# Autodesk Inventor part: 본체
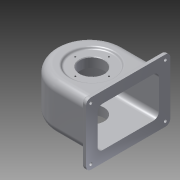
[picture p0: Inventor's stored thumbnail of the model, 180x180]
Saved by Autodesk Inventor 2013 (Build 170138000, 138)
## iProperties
Created: 2016-01
Part Number: 본체
Material: 알루미늄 6061
Document SubType Name: Modeling
Designer: dgall
Density: 2.71 g/cm^3
Mass: 812.893 g
Surface Area: 998.202 cm^2
Volume: 299.96 cm^3
Author: dgall
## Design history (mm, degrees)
sketch "스케치1"
  geometry: L1 (0, -57)-(64, -57); L2 (0, 57)-(64, 57); L3 (64, -57)-(64, 57); A1 r 57 centre (0, 0) between (0, 57) and (0, -57); 1 further point
  constraints: 6 end point, 2 point on circle, 2 tangent, 1 centre point, 1 coincident, 1 horizontal, 1 parallel, 1 perpendicular
  dimensions: "d4" = 114 diameter of A1; "d6" = 121 dimension on A1 L3
extrude "돌출1" new body sketch "스케치1" distance "d7" = 77; taper "d8" = 0 deg
feature "쉘1" dims "d9" = 6
sketch "스케치2"
  geometry: L1 (0, 0)-(64, 0) reference; L2 (0, -102)-(0, 0) reference; L3 (64, -102)-(0, -102) reference; A1 r 51 centre (64, -51) between (64, -102) and (64, 0) reference
extrude "돌출2" cut sketch "스케치2" distance "d10" = 1; taper "d11" = 0 deg
sketch "스케치3"
  geometry: L1 (64, 0)-(0, 0) reference; L2 (64, 102)-(64, 0) reference; L3 (0, 102)-(64, 102) reference; A1 r 51 centre (0, 51) between (0, 102) and (0, 0) reference
extrude "돌출3" cut sketch "스케치3" distance "d12" = 1; taper "d13" = 0 deg
sketch "스케치4"
  geometry: L1 (-64, 57)-(-64, -57) reference; L2 (-64, -57)-(0, -57) reference; L3 (-4, 24.205)-(-4, -25.457); L4 (0, 0)-(-23.424, 0); C1 r 31 at (-4, 0); A1 r 57 centre (0, 0) between (0, -57) and (0, 57) reference
  constraints: 4 end point, 2 perpendicular, 2 point on line, 1 centre point
  dimensions: "d131" = 60 distance between parallel lines of L1 L3; "d132" = 62 diameter of C1
extrude "돌출4" join sketch "스케치4" distance "d16" = 10; taper "d17" = 0 deg
sketch "스케치5"
  geometry: L1 (-4, 78.827)-(-4, -8.173); L2 (-64, 5)-(-64, 72) reference; L3 (-4, 58)-(16, 58); L4 (16, 58)-(16, 74); L5 (16, 58)-(24, 58); L6 (24, 58)-(35.747, 72); L7 (57, 77)-(0, 77) reference; L8 (-4, 74)-(30.899, 74); L9 (30.899, 74)-(33.416, 77); L10 (51, 72)-(0, 72) reference; L11 (35.747, 72)-(16, 72); L12 (-35, -10)-(27, -10) reference; 1 further point
  constraints: 16 end point, 6 point on line, 3 perpendicular, 2 parallel
  dimensions: "d26" = 60 distance between parallel lines of L2 L1; "d30" = 16 distance of L3.end L4.end; "d31" = 40 diameter of L4 L1; "d32" = 56 diameter of L5.end L1; "d34" = 3 distance between parallel lines of L7 L8; "d35" = 50 deg angle of L5 L6; "d36" = 5 distance between parallel lines of L6 L9; "d37" = 14 distance between parallel lines of L10 L5
revolve "회전1" sketch "스케치5" stored, may be unused: angle "d38" = 90 deg
sketch "스케치6"
  geometry: L1 (-24, 72)-(16, 72) reference; L2 (-4, 72)-(-4, 0); L3 (16, 72)-(16, 74); L4 (16, 74)-(30.899, 74); L5 (57, 77)-(0, 77) reference; L6 (35.747, 72)-(24, 58) reference; L7 (30.899, 74)-(33.416, 77); L8 (33.416, 77)-(-4, 77); L9 (-4, 77)-(-4, 72); L10 (16, 72)-(-4, 72); 1 further point
  constraints: 14 end point, 2 collinear, 2 parallel, 2 perpendicular, 2 point on line, 1 midpoint
  dimensions: "d39" = 3 distance between parallel lines of L5 L4; "d40" = 5 distance between parallel lines of L6 L7
revolve "회전2" sketch "스케치6" stored, may be unused: angle "d41" = 90 deg
sketch "스케치9"
  geometry: L1 (-72, 108)-(-5, 108) reference; L2 (-5, 108)-(-5, 6) reference; L3 (-5, 6)-(-72, 6) reference; L4 (-72, 6)-(-72, 108) reference; L5 (0, 114)-(0, 0) reference; L6 (0, 114)-(-77, 114) reference; L7 (-77, 0)-(-77, 114) reference; L8 (0, 0)-(-77, 0) reference; 1 further point
node "작업 평면4"
  node "작업 평면3"
sketch "스케치10"
  geometry: L1 (6, 5)-(108, 5) reference; L2 (108, 5)-(108, 72) reference; L3 (108, 72)-(6, 72) reference; L4 (6, 72)-(6, 5) reference; L5 (114, 77)-(114, 0) reference; L6 (114, 0)-(0, 0) reference; L7 (0, 0)-(0, 77) reference; L8 (0, 77)-(114, 77) reference; L9 (127, 90.5)-(-13, 90.5); L10 (-13, 90.5)-(-13, -13.5); L11 (-13, -13.5)-(127, -13.5); L12 (127, -13.5)-(127, 90.5); L13 (114, 38.5)-(0, 38.5); L14 (57, 77)-(57, 5); 1 further point
  constraints: 12 end point, 4 midpoint, 2 parallel, 1 horizontal, 1 perpendicular
  dimensions: "d54" = 104 distance of L11.end L9.start; "d56" = 140 distance of L9.start L9.end; "d57" = 70 distance between parallel lines of L12 L14; "d58" = 52 distance between parallel lines of L13 L9
extrude "돌출6" join sketch "스케치10" distance "d59" = 7; taper "d60" = 0 deg
fillet "모깎기1" dims "d61" = 14
fillet "모깎기3" dims "d63" = 9
fillet "모깎기4" dims "d64" = 3
fillet "모깎기5" dims "d68" = 1
fillet "모깎기6" dims "d69" = 8
fillet "모깎기7" dims "d70" = 3
sketch "스케치11"
  geometry: C1 r 2.5 at (-5.5, 5); C2 r 2.5 at (82.5, 5); C3 r 2.5 at (82.5, -119); C4 r 2.5 at (-5.5, -119); A1 r 5 centre (82.5, 5) between (87.5, 5) and (82.5, 10) reference; A2 r 5 centre (-5.5, 5) between (-5.5, 10) and (-10.5, 5) reference; A3 r 5 centre (-5.5, -119) between (-10.5, -119) and (-5.5, -124) reference; A4 r 5 centre (82.5, -119) between (82.5, -124) and (87.5, -119) reference; 1 further point
  constraints: 4 centre point, 4 coincident
  dimensions: "d71" = 5 diameter of C4; "d73" = 5 diameter of C1; "d74" = 5 diameter of C2; "d75" = 5 diameter of C3
extrude "돌출7" cut sketch "스케치11" stored distance "d76" = 7; taper "d77" = 0 deg
node "작업 평면5"
sketch "스케치12"
  geometry: L1 (-57, 63)-(57, 63) reference; L2 (-57, 14)-(-57, 63) reference; L3 (57, 14)-(-57, 14) reference; L4 (57, 14)-(57, 63) reference; L5 (-57, 38.5)-(57, 38.5); L6 (0, 63)-(0, 14); C1 r 6 at (0, 38.5); 1 further point
  constraints: 5 midpoint, 4 end point, 1 centre point
  dimensions: "d79" = 12 diameter of C1
extrude "돌출8" join sketch "스케치12" stored distance "d81" = 7; taper "d82" = 0 deg
sketch "스케치13"
  geometry: C1 r 6 at (0, 0) reference; 2 further points
  constraints: 1 coincident
hole "구멍1" sketch "스케치13" at (0, 0) diameter "d83" = 4.459; stored, may be unused: countersink angle "d87" = 90 deg, drill point angle "d89" = 118 deg; dims "d84" = 6, "d85" = 4, "d86" = 2, "d88" = 8
sketch "스케치15" dims "d102" = 56
  geometry: L1 (0, 0)-(-28, 0); C1 r 20 at (0, 0) reference; 2 further points
  constraints: 2 coincident, 2 end point, 1 horizontal, 1 horizontal alignment, 2 other
hole "구멍3" sketch "스케치15" at (-28, 0) diameter "d104" = 2.459; stored, may be unused: countersink angle "d108" = 90 deg, drill point angle "d110" = 118 deg; dims "d105" = 7, "d106" = 4, "d107" = 2, "d109" = 9
fillet "모깎기8" dims "d114" = 3
chamfer "모따기2" distance "d115" = 1; stored, may be unused: second distance "d116" = 2, angle "d117" = 45 deg
fillet "모깎기9" dims "d118" = 3
fillet "모깎기10" dims "d119" = 3
node "작업 평면6"
sketch "스케치16"
  geometry: L1 (100.528, 38.5)-(-99.777, 38.5); L2 (-34, 135.149)-(-34, -41.213); L3 (-64, -5.5)-(-64, 82.5) reference; L4 (0, 77)-(43, 77) reference; L5 (-30.398, 63.387)-(-30.398, 13.613); L6 (-30.398, 13.613)-(-37.602, 13.613); L7 (-37.602, 13.613)-(-37.602, 63.387); L8 (-37.602, 63.387)-(-30.398, 63.387); L9 (-34, 63.387)-(-34, 13.613); L10 (-30.398, 38.5)-(-37.602, 38.5); 1 further point
  constraints: 8 end point, 4 midpoint, 1 horizontal, 1 perpendicular, 2 other
  dimensions: "d121" = 30 distance between parallel lines of L3 L2; "d122" = 38.5 distance between parallel lines of L4 L1; "d123" = 0 distance between parallel lines of L2 L9; "d124" = 0 distance between parallel lines of L1 L10
feature "엠보싱1" sketch "스케치16" dims "d4" = 114, "d6" = 121, "d125" = 0.5, "d126" = 0
fillet "모깎기11" dims "d133" = 3
sketch "스케치20" dims "d144" = 48 (derived)
  geometry: L1 (0, 0)-(24, 0); C1 r 31 at (0, 0) reference; 2 further points
  constraints: 2 coincident, 2 end point, 1 horizontal, 1 horizontal alignment, 2 other
hole "구멍4" sketch "스케치20" at (24, 0) diameter "d145" = 2.459; stored, may be unused: countersink angle "d149" = 90 deg, drill point angle "d151" = 118 deg; dims "d146" = 6, "d147" = 4, "d148" = 2, "d150" = 8
sketch "스케치21"
  geometry: C1 r 31 at (0, 0) reference; C2 r 20 at (0, 0); 1 further point
  constraints: 1 centre point, 1 coincident
  dimensions: "d156" = 40 diameter of C2 (derived)
extrude "돌출10" cut sketch "스케치21" distance "d157" = 15; taper "d158" = 0 deg
node "솔리드1"
pattern_circular "원형 패턴2" dims angle "d112" = 360 deg
pattern_circular "원형 패턴4" dims angle "d160" = 360 deg
node "투영된 루프2"
node "절단 모서리 투영1"
other parameters: "d53" = -7, "d78" = -63, "d120" = 139
